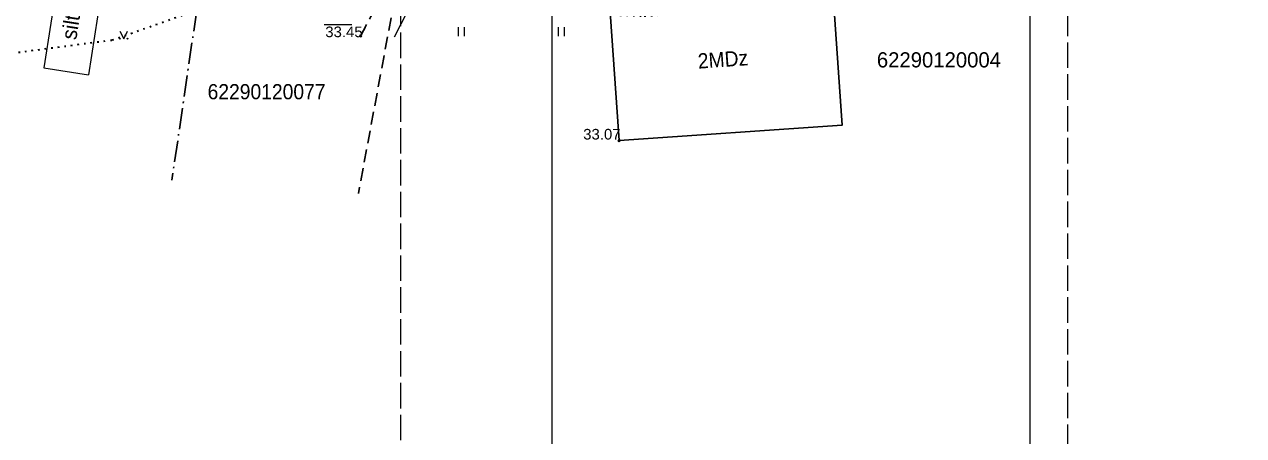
# Model space of a CAD drawing. Extents: x 380758 to 381729, y 283236 to 283533.
# Drawn here: x 381283.7 to 381364.1, y 283304.7 to 283331.8 of the extents above; entities that cross this region are included whole.
import ezdxf

# ---------------------------------------------------------------- set-up
doc = ezdxf.new("R2010")
doc.units = 0
doc.header["$LTSCALE"] = 0.28
for name, pattern in [('DOT_DASHED', [7.7, 5, -1.2, 0.3, -1.2]), ('DOTTED', [1.5, 0.3, -1.2]), ('LONG_DASHED', [7.5, 6, -1.5]), ('MEDIUM_DASHED', [4.5, 3, -1.5])]:
    doc.linetypes.add(name, pattern=pattern)
for name, color, linetype, lineweight in [('1', 7, 'Continuous', 13), ('23', 7, 'Continuous', 13), ('25', 7, 'DOTTED', 35), ('29', 7, 'DOT_DASHED', 25), ('37', 7, 'MEDIUM_DASHED', 13), ('39', 7, 'Continuous', 13), ('4', 7, 'Continuous', 13), ('40', 7, 'Continuous', 25), ('58', 7, 'Continuous', 25), ('63', 7, 'Continuous', 13)]:
    doc.layers.add(name, color=color, linetype=linetype, lineweight=lineweight)
doc.layers.add('59', color=7, linetype='Continuous')

msp = doc.modelspace()

# ---------------------------------------------------------------- linework, layer by layer
at = {"layer": '1'}
msp.add_line((381309.889, 283334.505), (381308.08, 283330.972), dxfattribs=at)
at = {"layer": '23'}
for p, q in [((381312.309, 283331.035), (381312.309, 283331.635)), ((381312.709, 283331.035), (381312.709, 283331.635)), ((381318.909, 283331.035), (381318.909, 283331.635)), ((381319.309, 283331.035), (381319.309, 283331.635))]:
    msp.add_line(p, q, dxfattribs=at)
msp.add_lwpolyline([(381289.996, 283331.369), (381290.246, 283330.869), (381290.496, 283331.369)], dxfattribs=at)
for centre, radius in [((381289.9953, 283330.8688), 0.028), ((381290.4953, 283330.8688), 0.0263)]:
    msp.add_circle(centre, radius, dxfattribs=at)
at = {"layer": '25'}
msp.add_lwpolyline([(380965.254, 283306.611), (380999.033, 283308.647), (381050.794, 283310.677), (381081.859, 283313.257), (381112.788, 283315.836), (381135.685, 283318.987), (381169.311, 283321.878), (381185.52, 283321.507), (381211.031, 283321.569), (381227.246, 283323.167), (381243.045, 283326.858), (381256.971, 283328.14), (381276.827, 283329.124), (381289.49, 283330.785), (381296.806, 283333.369), (381324.562, 283332.372), (381358.23, 283334.462), (381389.309, 283326.777)], dxfattribs=at)
at = {"layer": '29', "linetype": 'MEDIUM_DASHED'}
msp.add_line((381307.869, 283332.233), (381305.717, 283320.662), dxfattribs=at)
at = {"layer": '29'}
msp.add_lwpolyline([(381237.723, 283338.177), (381284.595, 283339.173), (381295.689, 283337.038), (381293.422, 283321.541)], dxfattribs=at)
at = {"layer": '37', "lineweight": 25}
msp.add_spline([(381305.861, 283331.052), (381307.093, 283333.314), (381308.993, 283336.307), (381314.083, 283342.617), (381320.758, 283347.149), (381323.818, 283347.761), (381326.707, 283347.877), (381328.405, 283347.988)], degree=3, dxfattribs=at)
at = {"layer": '39'}
msp.add_line((381288.836, 283334.373), (381287.921, 283328.491), dxfattribs=at)
msp.add_lwpolyline([(381285.905, 283334.854), (381284.986, 283328.948), (381287.921, 283328.491)], dxfattribs=at)
at = {"layer": '40'}
msp.add_lwpolyline([(381322.901, 283324.149), (381322.206, 283334.204), (381336.896, 283335.296), (381337.596, 283325.165)], close=True, dxfattribs=at)
at = {"layer": '58', "lineweight": 13}
msp.add_line((381303.454, 283331.795), (381305.284, 283331.795), dxfattribs=at)
at = {"layer": '58'}
for centre in [(381305.861, 283331.0521), (381322.901, 283324.1491)]:
    msp.add_circle(centre, 0.0534, dxfattribs=at)
at = {"layer": '63', "linetype": 'LONG_DASHED'}
msp.add_line((381352.477, 283259.645), (381352.477, 283469.645), dxfattribs=at)
at = {"layer": '63'}
msp.add_line((381349.977, 283467.145), (381349.977, 283262.145), dxfattribs=at)
at = {"layer": '63', "linetype": 'LONG_DASHED'}
msp.add_lwpolyline([(381728.995, 283532.875), (381308.495, 283532.875), (381308.495, 283235.875), (381728.995, 283235.875)], close=True, dxfattribs=at)
at = {"layer": '63'}
msp.add_lwpolyline([(381318.495, 283530.375), (381726.495, 283530.375), (381726.495, 283238.375), (381318.495, 283238.375)], close=True, dxfattribs=at)

# ---------------------------------------------------------------- texts
at = {"layer": '4'}
msp.add_text('silt.', height=1, rotation=81.158, dxfattribs=at).set_placement((381287.115, 283330.749))
at = {"layer": '4', "width": 0.95}
msp.add_text('2MDz', height=1, rotation=3.954, dxfattribs=at).set_placement((381328.125, 283328.891))
at = {"layer": '58', "width": 1.05}
for s, p in [('33.45', (381303.533, 283330.969)), ('33.07', (381320.535, 283324.22))]:
    msp.add_text(s, height=0.7, dxfattribs=at).set_placement(p)
at = {"layer": '59'}
msp.add_text('62290120004', height=1, dxfattribs=at).set_placement((381339.891, 283328.974))
at = {"layer": '59', "width": 0.95}
msp.add_text('62290120077', height=1, dxfattribs=at).set_placement((381295.776, 283326.874))

doc.saveas('drawing.dxf')
